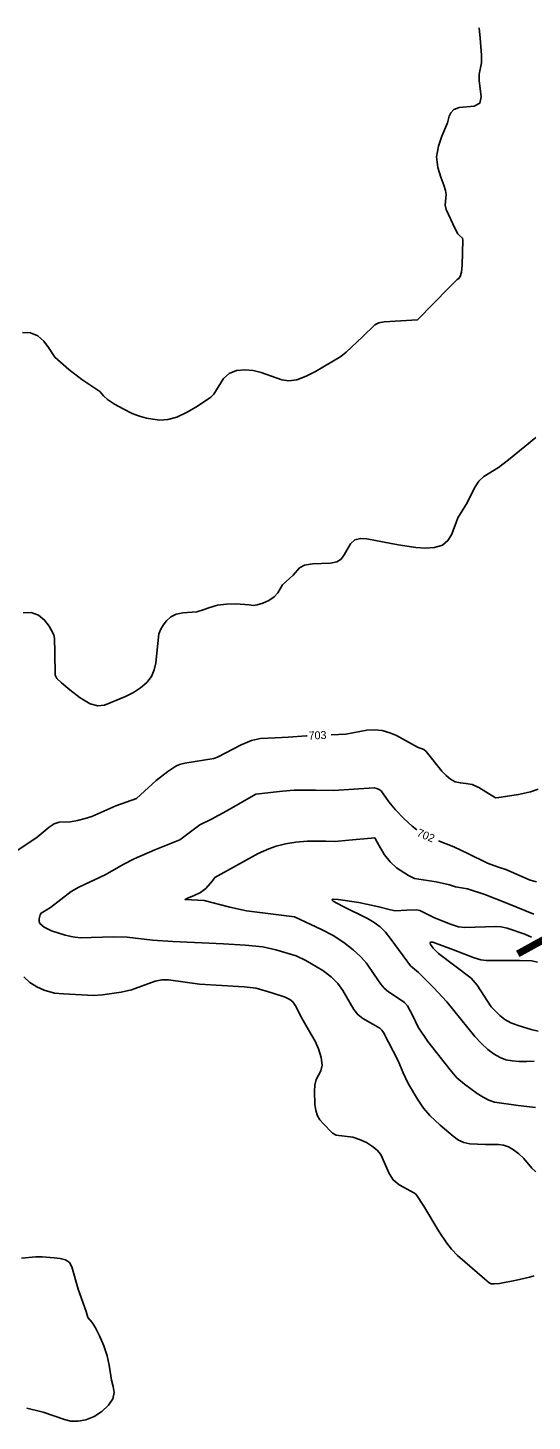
# Model space of a CAD drawing. Extents: x -291892836 to 2945206, y -477993085 to 1832792.
# Drawn here: x 1850527 to 1850779, y 544548 to 545245 of the extents above; entities that cross this region are included whole.
import ezdxf

# ---------------------------------------------------------------- set-up
doc = ezdxf.new("R2010")
doc.units = 0
for name, color, linetype in [('DT_X_Contour_Minor', 7, 'Continuous'), ('DT_X_Terrain_Ground_Line', 7, 'Continuous'), ('Level 19', 7, 'Continuous')]:
    doc.layers.add(name, color=color, linetype=linetype)

msp = doc.modelspace()

# ---------------------------------------------------------------- linework, layer by layer
at = {"layer": 'DT_X_Contour_Minor'}
for points in [[(1850742.67, 545120.46), (1850743.28, 545122.56), (1850743.62, 545126.1), (1850743.99, 545138.55), (1850743.76, 545139.58), (1850742.37, 545140.96), (1850741.57, 545141.73), (1850740.22, 545144.26), (1850735.61, 545153.91), (1850735.2, 545156.16), (1850735.47, 545159.79), (1850735.6, 545161.41), (1850735.37, 545163.36), (1850734.52, 545166.12), (1850732.99, 545170.04), (1850731.49, 545174.85), (1850730.89, 545180.17), (1850731.81, 545185.58), (1850733.6, 545190.55), (1850736.34, 545197.23), (1850737.23, 545200.55), (1850738.01, 545202.25), (1850739.53, 545203.87), (1850742.11, 545204.94), (1850749.72, 545205.63), (1850752.48, 545207.03), (1850753.23, 545210.15), (1850752.09, 545218.31), (1850752.17, 545221.52), (1850753.25, 545227.28), (1850753.33, 545231), (1850752.63, 545239.57), (1850752.18, 545244.7)], [(1850524.23, 545092.5), (1850528.2, 545092.33), (1850531.79, 545090.77), (1850534.81, 545088.05), (1850537.18, 545084.93), (1850540.31, 545080.07), (1850547.32, 545073.97), (1850553.77, 545068.99), (1850562.77, 545062.88), (1850564.52, 545060.74), (1850566.62, 545059), (1850570.12, 545056.7), (1850574.47, 545054.22), (1850578.84, 545052.05), (1850582.63, 545050.56), (1850585.99, 545049.64), (1850589.26, 545049.07), (1850592.75, 545048.71), (1850596.68, 545048.92), (1850601.24, 545050.12), (1850606.43, 545052.55), (1850611.55, 545055.56), (1850618.2, 545060.16), (1850619.62, 545061.65), (1850624.43, 545069.4), (1850627.34, 545072), (1850631.05, 545073.45), (1850635.21, 545073.84), (1850639.4, 545073.42), (1850643.29, 545072.46), (1850653.61, 545068.8), (1850657.14, 545068.31), (1850661.16, 545068.83), (1850665.77, 545070.56), (1850670.41, 545072.97), (1850683.03, 545080.41), (1850685.73, 545082.57), (1850693.9, 545090.31), (1850700.06, 545096.2), (1850702.04, 545097.3), (1850704.68, 545097.73), (1850721.35, 545098.71), (1850737.21, 545114.95), (1850741.22, 545119.01), (1850741.93, 545119.47), (1850742.67, 545120.46)], [(1850524.45, 544952.35), (1850528.54, 544952.48), (1850532.19, 544951.23), (1850535.16, 544948.75), (1850537.41, 544945.75), (1850539.82, 544941.29), (1850540.21, 544939.6), (1850540.38, 544932.69), (1850540.53, 544921.12), (1850541.37, 544919.46), (1850543.67, 544917.33), (1850547.83, 544913.85), (1850552.98, 544909.93), (1850557.95, 544906.91), (1850561.85, 544905.79), (1850565.04, 544906.21), (1850575.65, 544910.58), (1850579.53, 544912.52), (1850583.12, 544914.83), (1850586.18, 544917.5), (1850588.49, 544920.53), (1850589.92, 544923.88), (1850590.66, 544927.37), (1850592.25, 544941.91), (1850593.17, 544944.1), (1850594.46, 544946.26), (1850596.13, 544948.42), (1850598.27, 544950.35), (1850600.95, 544951.69), (1850604.19, 544952.27), (1850611.19, 544952.88), (1850614.4, 544953.83), (1850617.67, 544955.07), (1850621.45, 544956.15), (1850625.99, 544956.73), (1850630.66, 544956.86), (1850637.33, 544956.32), (1850639.31, 544956.09), (1850641.4, 544956.29), (1850644.19, 544957.14), (1850647.22, 544958.55), (1850649.84, 544960.36), (1850651.56, 544962.4), (1850653.96, 544966.38), (1850657.51, 544969.5), (1850659.27, 544971.12), (1850662.39, 544974.81), (1850665.01, 544976.16), (1850669.01, 544976.78), (1850677.93, 544977.21), (1850681.06, 544977.9), (1850683.22, 544979.22), (1850684.83, 544981.28), (1850687.92, 544986.82), (1850690.05, 544988.85), (1850692.89, 544989.55), (1850696.12, 544989.27), (1850711.72, 544986.26), (1850720.47, 544985.01), (1850725.31, 544984.7), (1850729.93, 544984.98), (1850733.82, 544986.17), (1850736.57, 544988.46), (1850738.35, 544991.31), (1850740.7, 544997.5), (1850741.53, 544999.84), (1850746.09, 545007.27), (1850749.77, 545014.79), (1850751.97, 545018.1), (1850754.53, 545020.42), (1850761.8, 545025.02), (1850766.87, 545028.84), (1850780.41, 545039.94)], [(1850519.39, 544832.01), (1850531.56, 544840.28), (1850537.39, 544845.26), (1850539.92, 544846.94), (1850542.39, 544847.66), (1850548.1, 544847.96), (1850551.67, 544848.53), (1850555.39, 544849.48), (1850558.8, 544850.63), (1850570.79, 544855.87), (1850581.09, 544859.61), (1850583.08, 544861.4), (1850590.92, 544868.62), (1850596.68, 544873.07), (1850600.74, 544875.79), (1850602.57, 544876.58), (1850605.24, 544877.23), (1850619.65, 544879.54), (1850621.46, 544880.25), (1850633.35, 544886.41), (1850638.56, 544888.5), (1850643.03, 544889.56), (1850650.27, 544889.9), (1850656.76, 544890.28), (1850666.03, 544890.93), (1850666.23, 544890.94)], [(1850678.22, 544891.42), (1850685.58, 544891.71), (1850696.04, 544893.65), (1850699.93, 544893.89), (1850703.78, 544893.47), (1850707.48, 544892.45), (1850710.96, 544890.96), (1850721.42, 544885.2), (1850724.52, 544884.06), (1850725.72, 544882.99), (1850733.48, 544873.28), (1850735.6, 544871.07), (1850737.84, 544869.17), (1850740.23, 544867.88), (1850742.79, 544867.37), (1850745.57, 544867.13), (1850748.65, 544866.47), (1850752.01, 544864.97), (1850760.26, 544859.92), (1850762.01, 544860.08), (1850771.82, 544861.6), (1850777.74, 544862.92), (1850781.69, 544864.19)], [(1850780.52, 544672.97), (1850778.49, 544674.74), (1850774.45, 544679.63), (1850771.99, 544681.97), (1850769.35, 544683.93), (1850766.74, 544685.39), (1850764.3, 544686.26), (1850761.76, 544686.67), (1850755.1, 544686.7), (1850747.51, 544686.92), (1850744.51, 544687.59), (1850741.87, 544688.83), (1850739.12, 544690.74), (1850732.64, 544696.26), (1850727.45, 544701.17), (1850724.3, 544704.83), (1850721.41, 544709.26), (1850716.73, 544717.17), (1850714.19, 544722.52), (1850711.69, 544728.39), (1850704.47, 544742.58), (1850703.63, 544743.81), (1850702.55, 544744.83), (1850699.12, 544746.84), (1850694, 544749.58), (1850691.53, 544751.55), (1850689.53, 544754.05), (1850684.17, 544763.61), (1850681.67, 544767.04), (1850678.34, 544770.43), (1850674.1, 544773.65), (1850665.69, 544778.63), (1850660.71, 544780.88), (1850650.72, 544783.88), (1850644.11, 544785.41), (1850635.32, 544786.26), (1850624.5, 544786.92), (1850599.29, 544788.04), (1850588.99, 544788.71), (1850576.36, 544790.26), (1850569.58, 544790.44), (1850553.01, 544789.99), (1850549.3, 544790.41), (1850545.41, 544791.23), (1850538.58, 544793.44), (1850534.98, 544795.32), (1850532.88, 544797.16), (1850532.42, 544798.12), (1850532.47, 544799.42), (1850532.91, 544801.38), (1850533.47, 544802.25), (1850535.91, 544803.7), (1850538.1, 544805.12), (1850548.46, 544813.06), (1850552.28, 544815.25), (1850565.46, 544821.42), (1850574.45, 544826.51), (1850579.91, 544829.35), (1850590.22, 544833.88), (1850602.75, 544838.85), (1850612.65, 544846.34), (1850618.13, 544849.1), (1850626.2, 544853.37), (1850640.62, 544861.71), (1850653.92, 544863.29), (1850659.72, 544863.73), (1850670.44, 544863.71), (1850679.39, 544863.51), (1850699.8, 544864.93), (1850701.13, 544864.62), (1850702.28, 544864.07), (1850703.19, 544863.31), (1850707.03, 544857.87), (1850710.42, 544853.97), (1850714.58, 544849.59), (1850718.69, 544845.7), (1850721.04, 544843.86)], [(1850780.3, 544705.13), (1850771.65, 544706.13), (1850759.74, 544707.82), (1850757.05, 544708.79), (1850754.18, 544710.23), (1850751.1, 544712.15), (1850744.88, 544716.79), (1850741, 544720.01), (1850737.61, 544723.88), (1850726.49, 544738.13), (1850721.72, 544745.27), (1850718.99, 544750.9), (1850716.44, 544755.85), (1850714.92, 544757.58), (1850711.21, 544760.18), (1850706.83, 544763), (1850704.77, 544764.73), (1850702.99, 544766.74), (1850699.8, 544771.53), (1850695.9, 544777.23), (1850693.02, 544780.47), (1850689.21, 544783.97), (1850684.55, 544787.56), (1850679.21, 544791.03), (1850673.45, 544794.16), (1850660, 544800.36), (1850658.57, 544800.64), (1850636.07, 544803.4), (1850627.59, 544805.26), (1850614.85, 544808.59), (1850605.29, 544809.09), (1850606.57, 544809.79), (1850609.56, 544810.94), (1850612.96, 544812.57), (1850615.72, 544814.63), (1850618.99, 544818.44), (1850620.16, 544820.02), (1850641.86, 544832.09), (1850647.09, 544834.48), (1850650.88, 544835.73), (1850655.46, 544836.88), (1850660.66, 544837.74), (1850666.2, 544838.19), (1850675.54, 544838.25), (1850680.19, 544838.11), (1850687.12, 544838.66), (1850700.02, 544839.96), (1850701.18, 544837.81), (1850702.67, 544834.99), (1850704.85, 544831.43), (1850707.65, 544827.86), (1850710.95, 544824.89), (1850716.87, 544821.05), (1850719.85, 544819.52), (1850730.76, 544817.88), (1850737.33, 544816.4), (1850740.27, 544815.41), (1850746.39, 544814.44), (1850755.05, 544811.64), (1850765.95, 544807.32), (1850779.48, 544801.76)], [(1850731.79, 544838.46), (1850731.9, 544838.41), (1850739.52, 544835.33), (1850746.43, 544832.06), (1850756.27, 544827.22), (1850761.37, 544825.34), (1850765.44, 544824.1), (1850777.54, 544818.7), (1850780.74, 544817.83)], [(1850778.35, 544790.25), (1850775.01, 544791.69), (1850766.14, 544794.68), (1850763.13, 544795.34), (1850760.49, 544795.54), (1850744.93, 544795.11), (1850741.89, 544795.47), (1850737.27, 544796.93), (1850729.57, 544800.07), (1850722.47, 544803.66), (1850720.87, 544803.9), (1850716.09, 544803.68), (1850710.25, 544803.48), (1850707.92, 544803.84), (1850702.09, 544805.44), (1850692.03, 544807.51), (1850681.72, 544809.15), (1850679.18, 544809.18), (1850678.68, 544808.9), (1850679.27, 544808.28), (1850683.93, 544805.8), (1850696.37, 544799.65), (1850699.79, 544797.66), (1850702.68, 544795.49), (1850705.42, 544792.72), (1850708.29, 544789.12), (1850717.89, 544775.98), (1850721.88, 544772.55), (1850729.37, 544765.17), (1850735.99, 544757.85), (1850749.96, 544740.53), (1850753.28, 544737.06), (1850756.54, 544734.08), (1850759.65, 544731.72), (1850762.58, 544730.07), (1850765.51, 544729.02), (1850768.65, 544728.4), (1850772.17, 544728.09), (1850775.9, 544728.06), (1850779.61, 544728.31)], [(1850781.25, 544777.72), (1850778.44, 544778.34), (1850772.36, 544778.53), (1850755.61, 544778.56), (1850752.96, 544778.88), (1850749.58, 544779.85), (1850739.32, 544783.84), (1850729.06, 544787.83), (1850727.82, 544787.71), (1850727.62, 544787.31), (1850727.82, 544786.64), (1850729.16, 544784.74), (1850731.88, 544782.16), (1850748.2, 544769.68), (1850751.17, 544766.27), (1850758.19, 544755.39), (1850762.46, 544751.08), (1850765.01, 544749.16), (1850768.05, 544747.47), (1850771.6, 544746.03), (1850778.14, 544744.12), (1850781.61, 544743.23)], [(1850689.05, 544690.23), (1850680.76, 544691.22), (1850678.87, 544692.33), (1850674.13, 544697.25), (1850672.6, 544698.93), (1850671.36, 544700.97), (1850670.57, 544703.58), (1850670.16, 544706.62), (1850669.92, 544713.22), (1850670.14, 544716.34), (1850670.81, 544719.05), (1850673.16, 544723.47), (1850673.72, 544726.29), (1850673.22, 544730.11), (1850671.91, 544734.38), (1850670.26, 544738.32), (1850666.99, 544743.92), (1850663.63, 544749.75), (1850660.43, 544755.91), (1850659.11, 544757.87), (1850657.58, 544759.17), (1850655.38, 544760.22), (1850648.65, 544762.43), (1850640.81, 544764.69), (1850634.78, 544765.35), (1850612.53, 544766.68), (1850597.09, 544768.99), (1850593.72, 544768.93), (1850590.42, 544768.31), (1850578.63, 544763.97), (1850573.42, 544762.81), (1850564.1, 544761.49), (1850559.66, 544761.14), (1850544.68, 544761.85), (1850540.21, 544762.22), (1850535.03, 544763.8), (1850531.36, 544765.41), (1850527.77, 544767.62), (1850524.75, 544770.38)], [(1850779.63, 544620.96), (1850777.35, 544620.36), (1850770.79, 544618.77), (1850762.37, 544617.21), (1850759.74, 544616.94), (1850758.17, 544617.06), (1850757.14, 544617.5), (1850754.74, 544619.49), (1850741.37, 544631.15), (1850738.35, 544634.32), (1850735.99, 544637.26), (1850732.25, 544643.04), (1850724.58, 544655.86), (1850720.69, 544661.71), (1850719.83, 544662.34), (1850712.19, 544666.41), (1850709.26, 544668.92), (1850707.17, 544672.13), (1850703.04, 544681.58), (1850701.25, 544683.77), (1850698.89, 544685.71), (1850695.88, 544687.57), (1850692.49, 544689.16), (1850689.05, 544690.23)], [(1850523.59, 544629.85), (1850530.74, 544630.53), (1850533.96, 544630.55), (1850540.02, 544629.98), (1850542.95, 544629.58), (1850545.58, 544628.91), (1850547.58, 544627.65), (1850548.79, 544625.55), (1850552.01, 544614.32), (1850555.9, 544603.15), (1850556.84, 544600.22), (1850558.94, 544597.64), (1850560.62, 544595.05), (1850562.65, 544591.01), (1850564.69, 544586.05), (1850566.37, 544580.96), (1850567.41, 544576.36), (1850568.67, 544568.78), (1850569.44, 544565.61), (1850569.87, 544562.61), (1850569.25, 544559.55), (1850567.12, 544556.31), (1850563.81, 544553.21), (1850559.88, 544550.69), (1850555.82, 544549.09), (1850551.89, 544548.37), (1850548.31, 544548.43), (1850545.18, 544549.13), (1850534.53, 544552.85), (1850526.37, 544554.89)]]:
    msp.add_lwpolyline(points, dxfattribs=at)

# ---------------------------------------------------------------- texts
at = {"layer": 'DT_X_Terrain_Ground_Line'}
msp.add_text('700', height=33, rotation=28.92291, dxfattribs=at).set_placement((1850784.54, 544753.48))
at = {"layer": 'Level 19'}
for s, rotation, p in [('703', 2.29756, (1850667.08, 544888.97)), ('702', 337.33463, (1850720.66, 544840.94))]:
    msp.add_text(s, height=4, rotation=rotation, dxfattribs=at).set_placement(p)

doc.saveas('drawing.dxf')
